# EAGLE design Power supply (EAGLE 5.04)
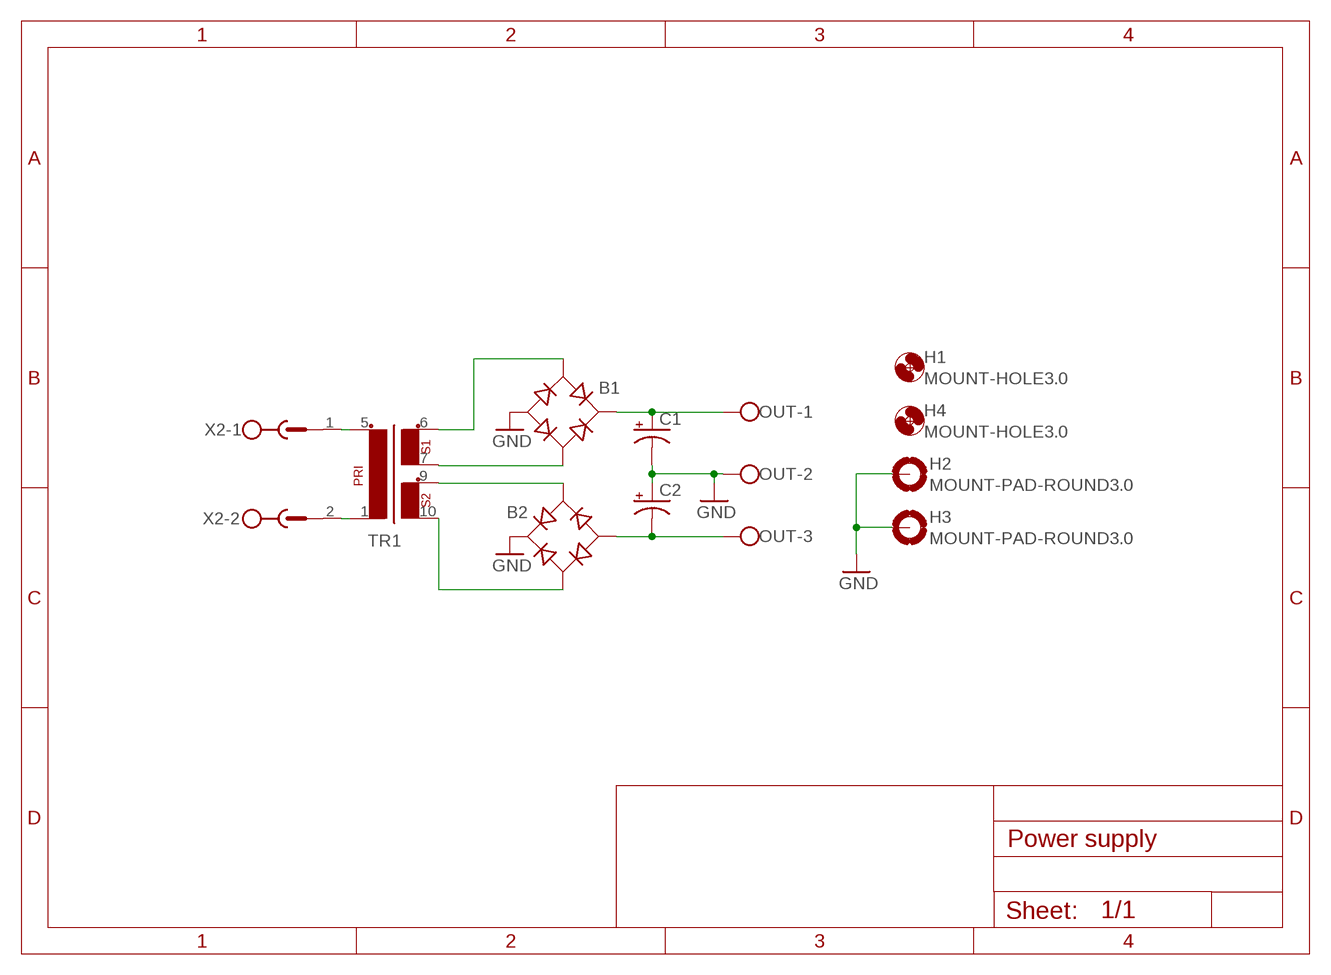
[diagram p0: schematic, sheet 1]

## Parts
B1  RB1A  [RB1A]
B2  RB1A  [RB1A]
C1  CPOL-USE5-10.5  [E5-10,5]
C2  CPOL-USE5-10.5  [E5-10,5]
H1  MOUNT-HOLE3.0  [3,0]
H2  MOUNT-PAD-ROUND3.0  [3,0-PAD]
H3  MOUNT-PAD-ROUND3.0  [3,0-PAD]
H4  MOUNT-HOLE3.0  [3,0]
OUT  W237-3E  [W237-3E]
TR1  EI30-2  [EI30-2]
X2  MSTBV2  [MSTBV2]

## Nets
GND: B1.- B2.+ C1.- C2.+ H2.B3,0(MOUNT) H3.B3,0(MOUNT) OUT.2
N$1: B1.AC2 TR1.7
N$2: B1.AC1 TR1.6
N$3: B2.AC1 TR1.9
N$4: B2.AC2 TR1.10
N$5: B1.+ C1.+ OUT.1
N$6: B2.- C2.- OUT.3
N$7: TR1.5 X2.1
N$8: TR1.1 X2.2

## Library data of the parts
B1 B2 = rectifier:RB1A: RECTIFIER 1 A
C1 C2 = rcl:CPOL-US: POLARIZED CAPACITOR, American symbol
H1 H4 = holes:MOUNT-HOLE: MOUNTING HOLE with drill center marker
H2 H3 = holes:MOUNT-PAD-ROUND: MOUNTING PAD, round
OUT = con-wago-508:W237-3E: WAGO SREW CLAMP
TR1 = trafo:EI30-2: TRANSFORMER 1 primary winding, 2 secondary windings ERA
X2 = con-phoenix-500:MSTBV2: PHOENIX

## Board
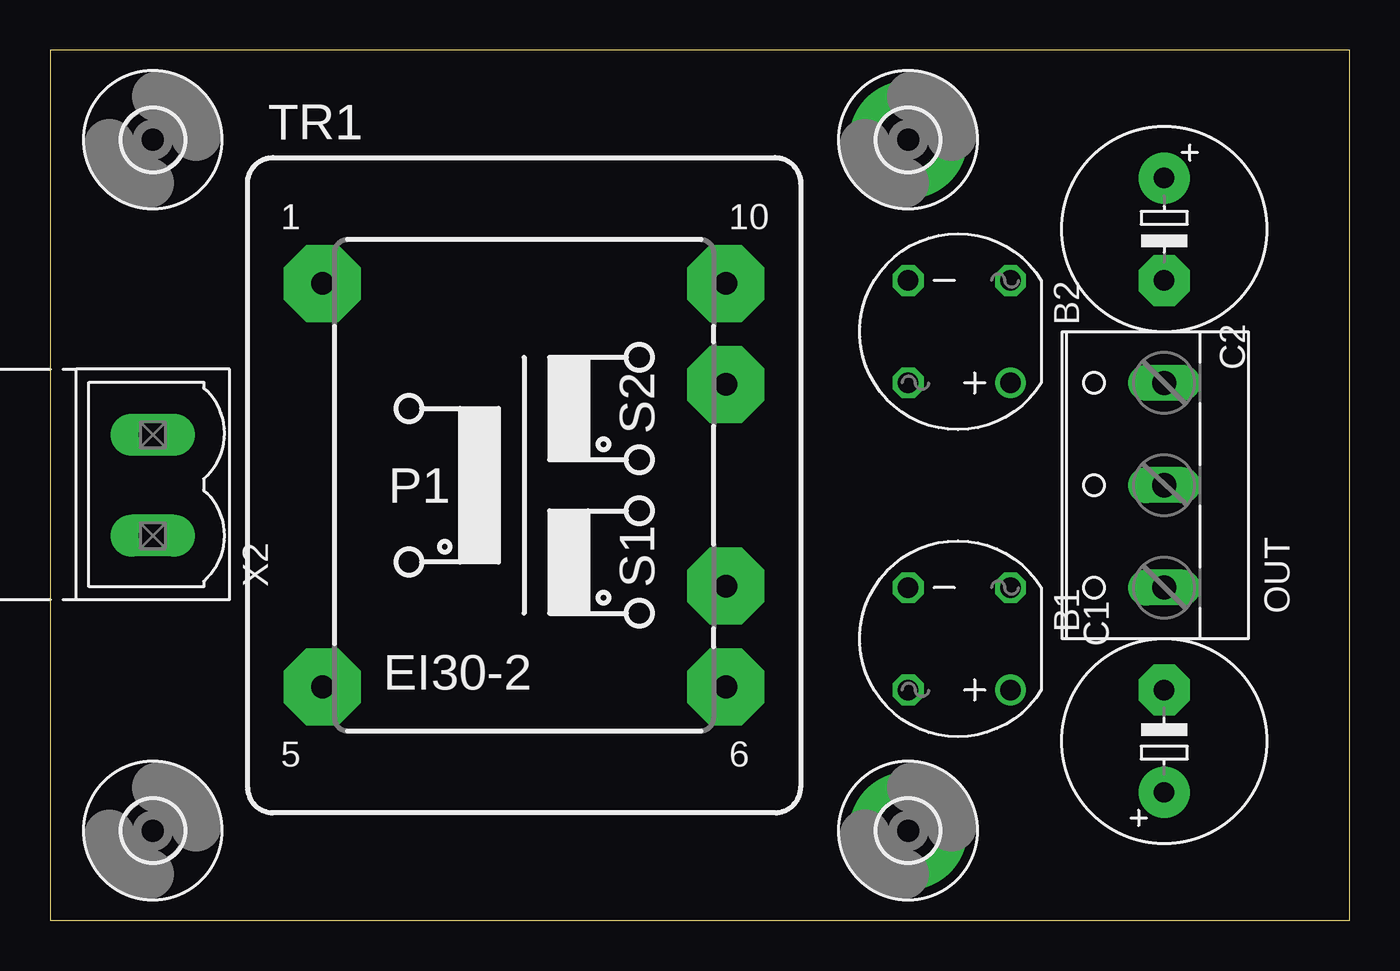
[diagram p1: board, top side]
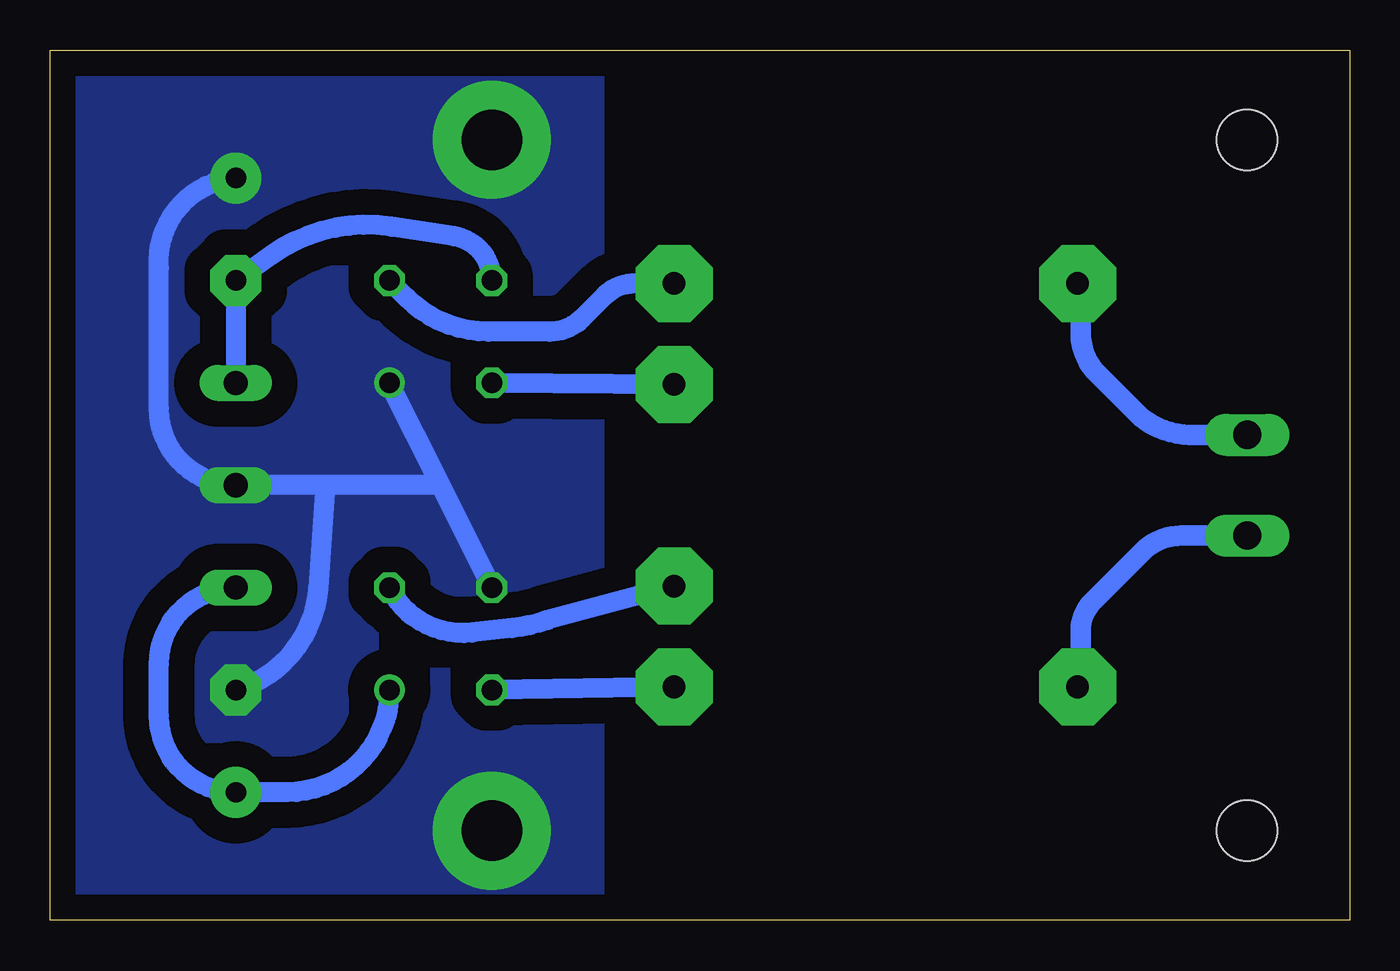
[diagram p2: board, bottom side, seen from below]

Size 64.44 x 43.17 mm. Coordinates in mm from the lower left corner, seen from the top.
Outline: 0,0 64.44,0 64.44,43.17 0,43.17 0,0
Copper layers (1*16): Top 0.035mm / dielectric 1.5mm / Bottom 0.035mm
Design rules "default *": minimum track width 10mil, minimum drill 24mil, track to track 8mil, track to pad 8mil, pad to pad 8mil, via to via 8mil, smd to smd 8mil, copper to edge 5mil, drill to drill 8mil, minimum pad ring 10mil, minimum via ring 8mil, stop-mask expansion 4mil, vias tented up to drill 0mil, thermal gap 10mil

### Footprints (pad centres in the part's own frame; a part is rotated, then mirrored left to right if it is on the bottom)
RB1A = drill 1.016 round: + -2.54,2.54 | drill 1.016 octagon: - 2.54,-2.54; AC1 2.54,2.54; AC2 -2.54,-2.54
E5-10,5 = drill 1.016 pad 2.54 round: + -2.54,0 | drill 1.016 pad 2.54 octagon: - 2.54,0
3,0 = hole 3: 0,0
3,0-PAD = drill 3 pad 5.842 round: B3,0 0,0
W237-3E = drill 1.194 long: 1 -5.08,-0.635; 2 0,-0.635; 3 5.08,-0.635
EI30-2 = drill 1.118 pad 3.81 octagon: 1 -10.008,10.008; 5 -10.008,-10.008; 6 10.008,-10.008; 7 10.008,-5.004; 9 10.008,5.004; 10 10.008,10.008
MSTBV2 = drill 1.397 long: 1 -2.5,0; 2 2.5,0

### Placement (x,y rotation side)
B1  45.09,13.97 180 top
B2  45.09,29.21 180 top
C1  55.24,8.89 90 top
C2  55.24,34.29 270 top
H1  5.08,4.45 0 top
H2  42.55,4.45 0 top
H3  42.55,38.73 0 top
H4  5.08,38.73 0 top
OUT  54.61,21.59 90 top
TR1  23.5,21.59 0 top
X2  5.08,21.59 90 top

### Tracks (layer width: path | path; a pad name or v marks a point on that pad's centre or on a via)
GND
  Bottom 1: B1.- 45.09,21.59 | 45.09,21.59 B2.+ | 45.09,21.59 50.8,21.59 | 50.8,21.59 OUT.2 arc90 59.05,25.4 59.05,32.38 arc90 C2.+ | 50.8,21.59 51.16,16.48 arc67 55.03,11.5 C1.-
  pour Bottom (isolate 1.27, rank 5, no thermals): 37.47,44.45 37.47,-0.64 65.41,-0.64 65.41,44.45
N$1
  Bottom 1: TR1.7 39.79,14.89 arc12 41.54,14.51 43.53,14.28 arc70 B1.AC2
N$2
  Bottom 1: TR1.6 B1.AC1
N$3
  Bottom 1: TR1.9 B2.AC1
N$4
  Bottom 1: TR1.10 35.49,31.6 arc-45 36.96,30.99 38.06,29.88 arc45 39.68,29.21 42.72,29.21 arc45 46.76,30.88 B2.AC2
N$5
  Bottom 1: B1.+ arc90 52.7,6.35 C1.+ arc90 59.05,10.16 59.05,12.7 arc90 OUT.1
N$6
  Bottom 1: OUT.3 C2.- 53.49,33 arc44 47.53,34.42 44.43,33.95 arc81 B2.-
N$7
  Bottom 1: TR1.5 13.34,11.73
  Bottom 1.016: X2.1 8.35,19.09 arc-45 10.29,18.28 12.75,15.83 arc-45 13.34,14.41 13.34,11.73
N$8
  Bottom 1: 13.34,31.45 TR1.1
  Bottom 1.016: X2.2 7.92,24.09 arc45 10.59,25.19 12.5,27.11 arc45 13.34,29.12 13.34,31.45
